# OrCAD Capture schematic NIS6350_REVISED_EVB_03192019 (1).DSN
size C
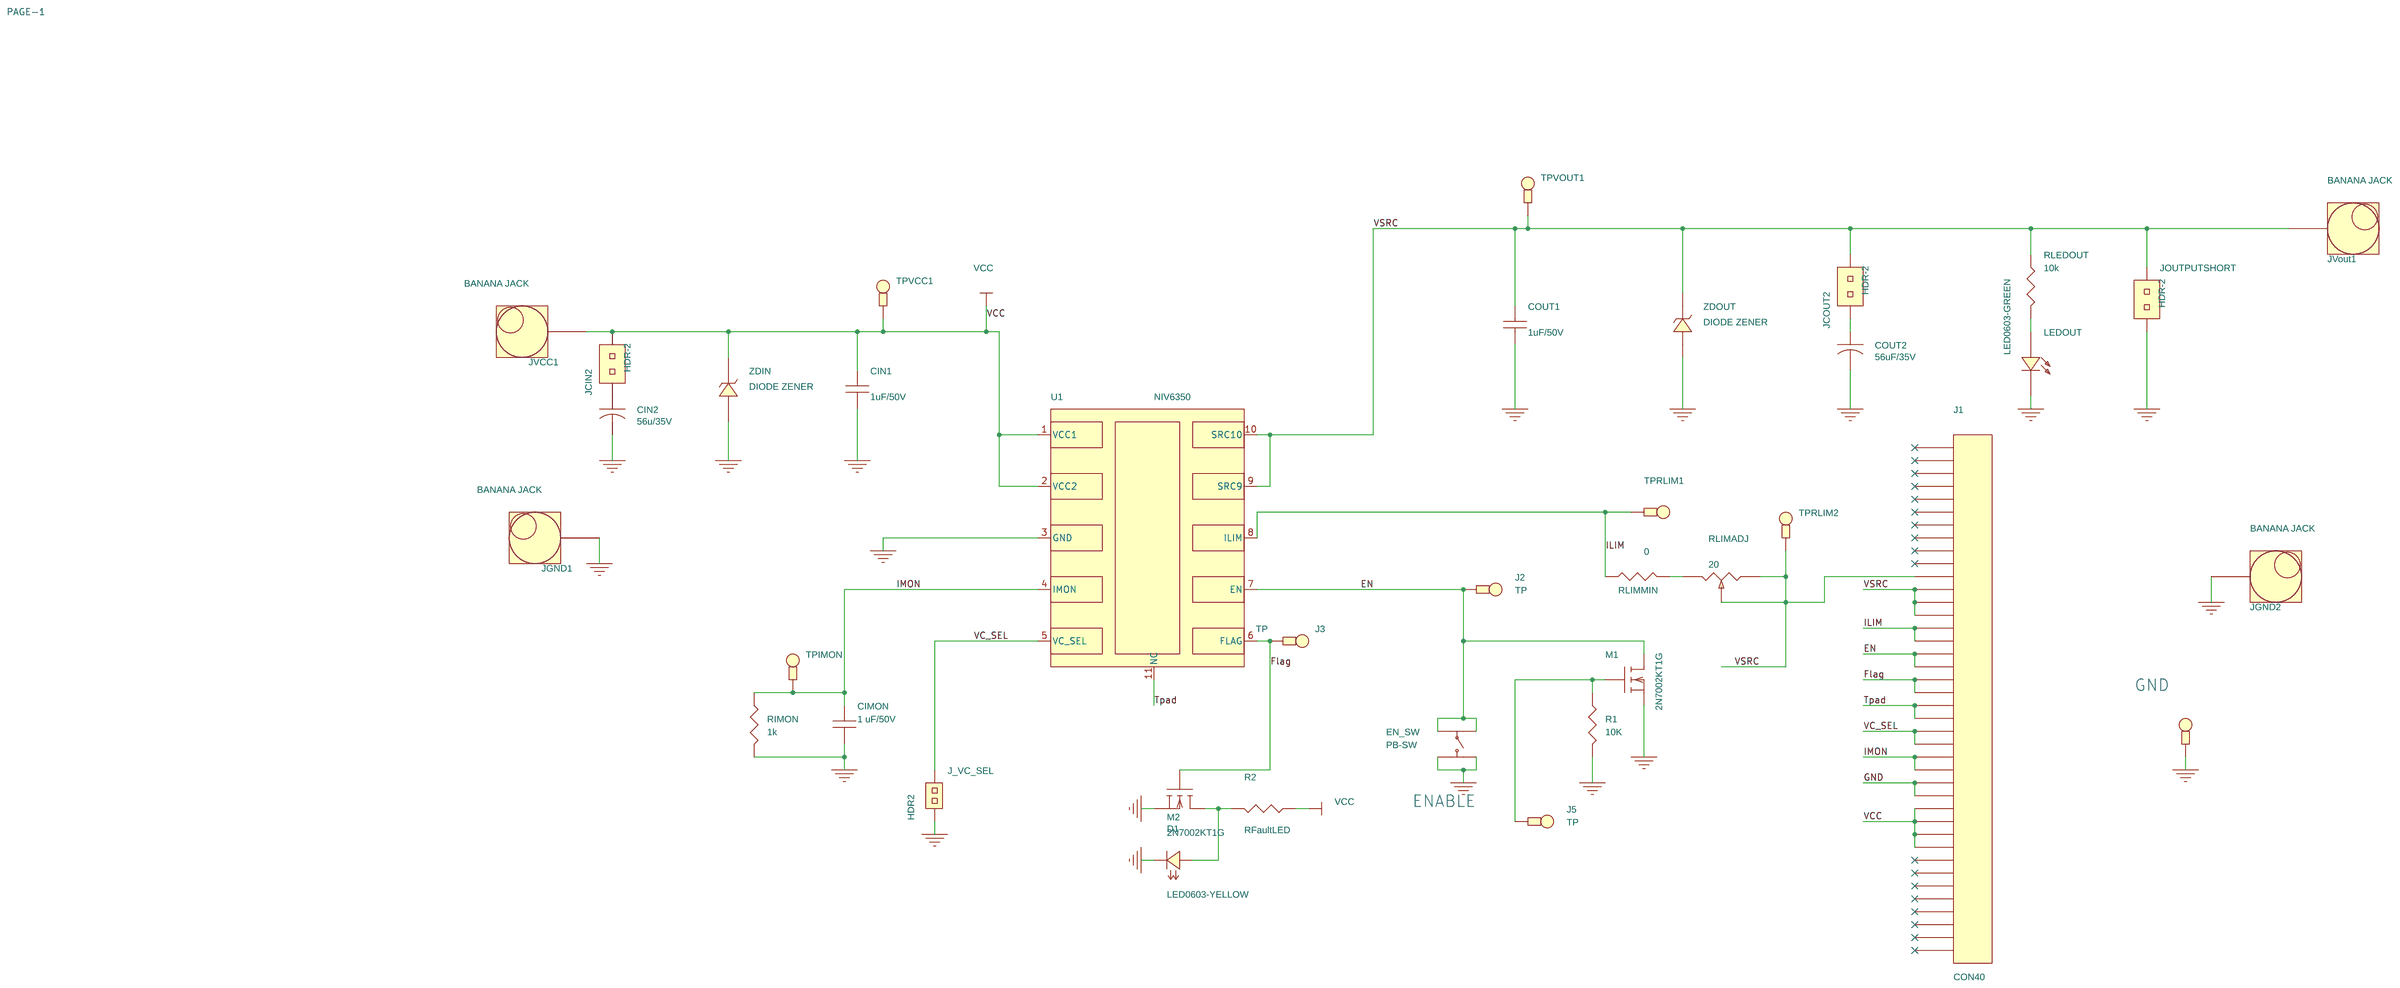
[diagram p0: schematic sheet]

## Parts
CIMON  1 uF/50V  [0805]
CIN1  1uF/50V  [0805]
CIN2  56u/35V  [cap_smd_8p3x8p3]
COUT1  1uF/50V  [0805]
COUT2  56uF/35V  [cap_smd_8p3x8p3]
D1  LED0603-YELLOW  [LED0603]
EN_SW  PB-SW  [SW-TAC-SPST]
J1  CON40  [abc20drt]
J2  TP  [TP-HOOK]
J3  TP  [TP-HOOK]
J5  TP  [TP-HOOK]
J_VC_SEL  HDR2  [HEADER-2]
JCIN2  HDR-2  [HEADER-2]
JCOUT2  HDR-2  [HEADER-2]
JGND1  BANANA JACK  [banana_via]
JGND2  BANANA JACK  [banana_via]
JOUTPUTSHORT  HDR-2  [HEADER-2]
JVCC1  BANANA JACK  [banana_via]
JVout1  BANANA JACK  [banana_via]
LEDOUT  LED0603-GREEN  [LED0603]
M1  2N7002KT1G  [SOT-23]
M2  2N7002KT1G  [SOT-23]
R1  10K  [0805]
R2  RFaultLED  [0805]
RIMON  1k  [0805]
RLEDOUT  10k  [0805]
RLIMADJ  20  [3214x_trim_pot]
RLIMMIN  0  [0805]
TPGND1  TP-HOOK  [TP-HOOK]
TPIMON  TP-HOOK  [TP-HOOK]
TPRLIM1  TP-HOOK  [TP-HOOK]
TPRLIM2  TP-HOOK  [TP-HOOK]
TPVCC1  TP-HOOK  [TP-HOOK]
TPVOUT1  TP-HOOK  [TP-HOOK]
U1  NIV6350  [dfn-10-3x3-05mm]
ZDIN  DIODE ZENER  [0805]
ZDOUT  DIODE ZENER  [0805]

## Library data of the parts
CIMON CIN1 COUT1 = CAP_NP: CAP CER 0.1UF 50V 10% X7R 0603; DIGIKEY: 399-5089-1-ND; Manufacturer: Kemet; Manufacturer Part #: C0603C104K5RACTU; Price: 0.10000
CIN2 COUT2 = CAP: CAP ALUM POLY 56UF 20% 35V SMD; DIGIKEY: P121400CT-ND; Manufacturer: Panasonic Electronic Components; Manufacturer Part #: EEH-ZK1V560P; Price: 1.8000
D1 = LED_0: LED YELLOW CLEAR THIN 0603 SMD; DIGIKEY: 160-1448-1-ND; Manufacturer: Lite-On Inc; Manufacturer Part #: LTST-C191KSKT; Price: 0.248
EN_SW = PUSH-BUTTON-SW_2: SWITCH TACTILE SPST-NO 0.05A 12V; DIGIKEY: EG4369-ND; Manufacturer: E-Switch; Manufacturer Part #: TL1105FF160Q; Price: 0.19000
J1 = CON40_0: CONN EDGE DUAL FMALE 40POS 0.100; DIGIKEY: S3314-ND; Manufacturer: Sullins Connector Solutions; Manufacturer Part #: EBC20DRTH; Price: 5.05
J2 J3 J5 = TP-HOOK: TEST POINT PC MINI .040"D YELLOW; DIGIKEY: 5004K-ND; Manufacturer: Keystone Electronics; Manufacturer Part #: 5004; Price: 0.34000
J_VC_SEL = HEADER_2_0: CONN HEADER VERT SGL 2POS GOLD; DIGIKEY: 3M9447-ND; Manufacturer: 3M; Manufacturer Part #: 961102-6404-AR; Price: 0.16000
JCIN2 JCOUT2 JOUTPUTSHORT = HEADER_2_1: CONN HEADER VERT SGL 2POS GOLD; DIGIKEY: 3M9447-ND; Manufacturer: 3M; Manufacturer Part #: 961102-6404-AR; Price: 0.16000
JGND1 JGND2 JVCC1 JVout1 = Banana_Conn: JACK NON-INSULATED .350"; DIGIKEY: 36-575-8-ND; Manufacturer: Keystone Electronics; Manufacturer Part #: 575-8; Manufacturer Part#: 575-8; Price: 0.99
LEDOUT = LED_0_v2: LED YELLOW CLEAR THIN 0603 SMD; DIGIKEY: 160-1448-1-ND; Manufacturer: Lite-On Inc; Manufacturer Part #: LTST-C191KSKT; Price: 0.248
M1 M2 = MMDF4N01HD_ON_1: MOSFET N-CH 60V 320MA SOT-23; DIGIKEY: 2N7002KT1GOSCT-ND; Manufacturer: ON Semiconductor; Price: 0.23000
R1 RIMON = RESISTOR: RES 10K OHM 1/10W 5% 0603 SMD; DIGIKEY: P10KGCT-ND; Manufacturer: Panasonic Electronic Components; Manufacturer Part #: ERJ-3GEYJ103V; Price: 0.10000
R2 = RESISTOR: RES 1K OHM 1/10W 5% 0603 SMD; DIGIKEY: P1.0KGCT-ND; Manufacturer: Panasonic Electronic Components; Manufacturer Part #: ERJ-3GEYJ102V; Price: 0.0126
RLEDOUT = RESISTOR: RES 680 OHM 1/10W 5% 0603 SMD; DIGIKEY: P680GCT-ND; Manufacturer: Panasonic Electronic Components; Manufacturer Part #: ERJ-3GEYJ681V; Price: 0.01260
RLIMADJ = POT_SM: TRIMMER 100 OHM 0.25W GW TOP ADJ; DIGIKEY: 3214X-1-101ECT-ND; Manufacturer: Bourns Inc.; Manufacturer Part #: 3214X-1-101E; Manufacturer part#: PV36W201C01B00; Price: 3.24; Supplier: www.digikey.com; Supplier part#: 3214X-1-101ECT-ND
RLIMMIN = RESISTOR: RES 20 OHM 1% 1/4W 0805; DIGIKEY: RNCP0805FTD20R0CT-ND; Manufacturer: Stackpole Electronics Inc.; Manufacturer Part #: RNCP0805FTD20R0; Price: 0.10
TPGND1 = TP-HOOK: TEST POINT PC MINI .040"D BLACK; DIGIKEY: 5001K-ND; Manufacturer: Keystone Electronics; Manufacturer Part #: 5001; Price: 0.34000
TPIMON TPRLIM1 TPRLIM2 TPVCC1 TPVOUT1 = TP-HOOK: TEST POINT PC MINI .040"D RED; DIGIKEY: 5000K-ND; Manufacturer: Keystone Electronics; Manufacturer Part #: 5000; Price: 0.34000
U1 = NIV6350
ZDIN ZDOUT = DIODE_ZENER: DIODE ZENER 33V 500MW SOD123; DIGIKEY: MMSZ5257BT1GOSCT-ND; Manufacturer: ON Semiconductor; Manufacturer Part #: MMSZ5257BT1G; Price: 0.25

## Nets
GND: CIMON.2 CIN1.2 CIN2.2 COUT1.2 COUT2.2 D1.1(CATHODE) EN_SW.1 EN_SW.2 J1.27 J1.28 J_VC_SEL.2 JGND1.1 JGND2.1 JOUTPUTSHORT.2 LEDOUT.1(CATHODE) M1.2(S) M2.2(S) R1.2 RIMON.2 TPGND1.1 U1.3(GND) ZDIN.2(ANODE) ZDOUT.2(ANODE)
VCC: CIN1.1 J1.29 J1.30 J1.31 J1.32 JCIN2.1 JVCC1.1 R2.1 TPVCC1.1 U1.1(VCC1) U1.2(VCC2) ZDIN.1(CATHODE)
EN: EN_SW.3 EN_SW.4 J1.17 J1.18 J2.1 M1.3(D) U1.7(EN)
Flag: J1.19 J1.20 J3.1 M2.1(G) U1.6(FLAG)
ILIM: J1.15 J1.16 RLIMMIN.2 TPRLIM1.1 U1.8(ILIM)
IMON: CIMON.1 J1.25 J1.26 RIMON.1 TPIMON.1 U1.4(IMON)
Tpad: J1.21 J1.22 U1.11(NC)
VC_SEL: J1.23 J1.24 J_VC_SEL.1 U1.5(VC_SEL)
VSRC: COUT1.1 J1.11 J1.12 J1.13 J1.14 JCOUT2.1 JOUTPUTSHORT.1 JVout1.1 RLEDOUT.1 RLIMADJ.1(A) RLIMADJ.2(WIPER) TPRLIM2.1 TPVOUT1.1 U1.9(SRC9) U1.10(SRC10) ZDOUT.1(CATHODE)
N12391538: LEDOUT.2(ANODE) RLEDOUT.2
N12393096: RLIMADJ.3(B) RLIMMIN.1
N14404692: COUT2.1 JCOUT2.2
N14450563: D1.2(ANODE) M2.3(D) R2.2
N14454265: J5.1 M1.1(G) R1.1
N14468066: CIN2.1 JCIN2.2

Not connected (* = marked no-connect by the designer): J1 1* 2* 3* 4* 5* 6* 7* 8* 9* 10* 33* 34* 35* 36* 37* 38* 39* 40*

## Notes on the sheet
- PAGE-1
- GND
- ENABLE
